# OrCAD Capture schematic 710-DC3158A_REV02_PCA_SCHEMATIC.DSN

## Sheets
1 PAGE1
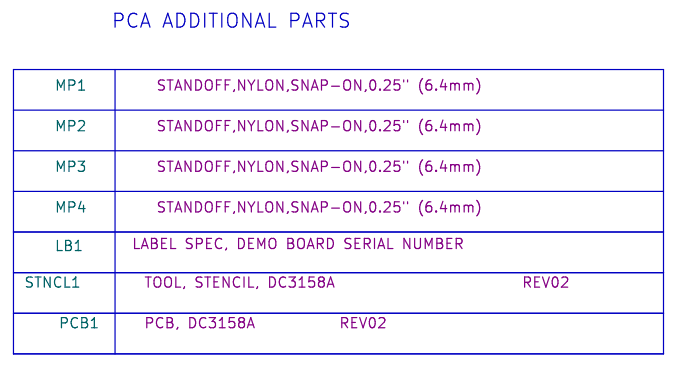
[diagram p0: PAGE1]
2 LT3041ADE: size B; title: LINEAR REGULATOR WITH VOIC CONTROL; note: 20V, 1A ULTRALOW NOISE, ULTRAHIGH PSRR
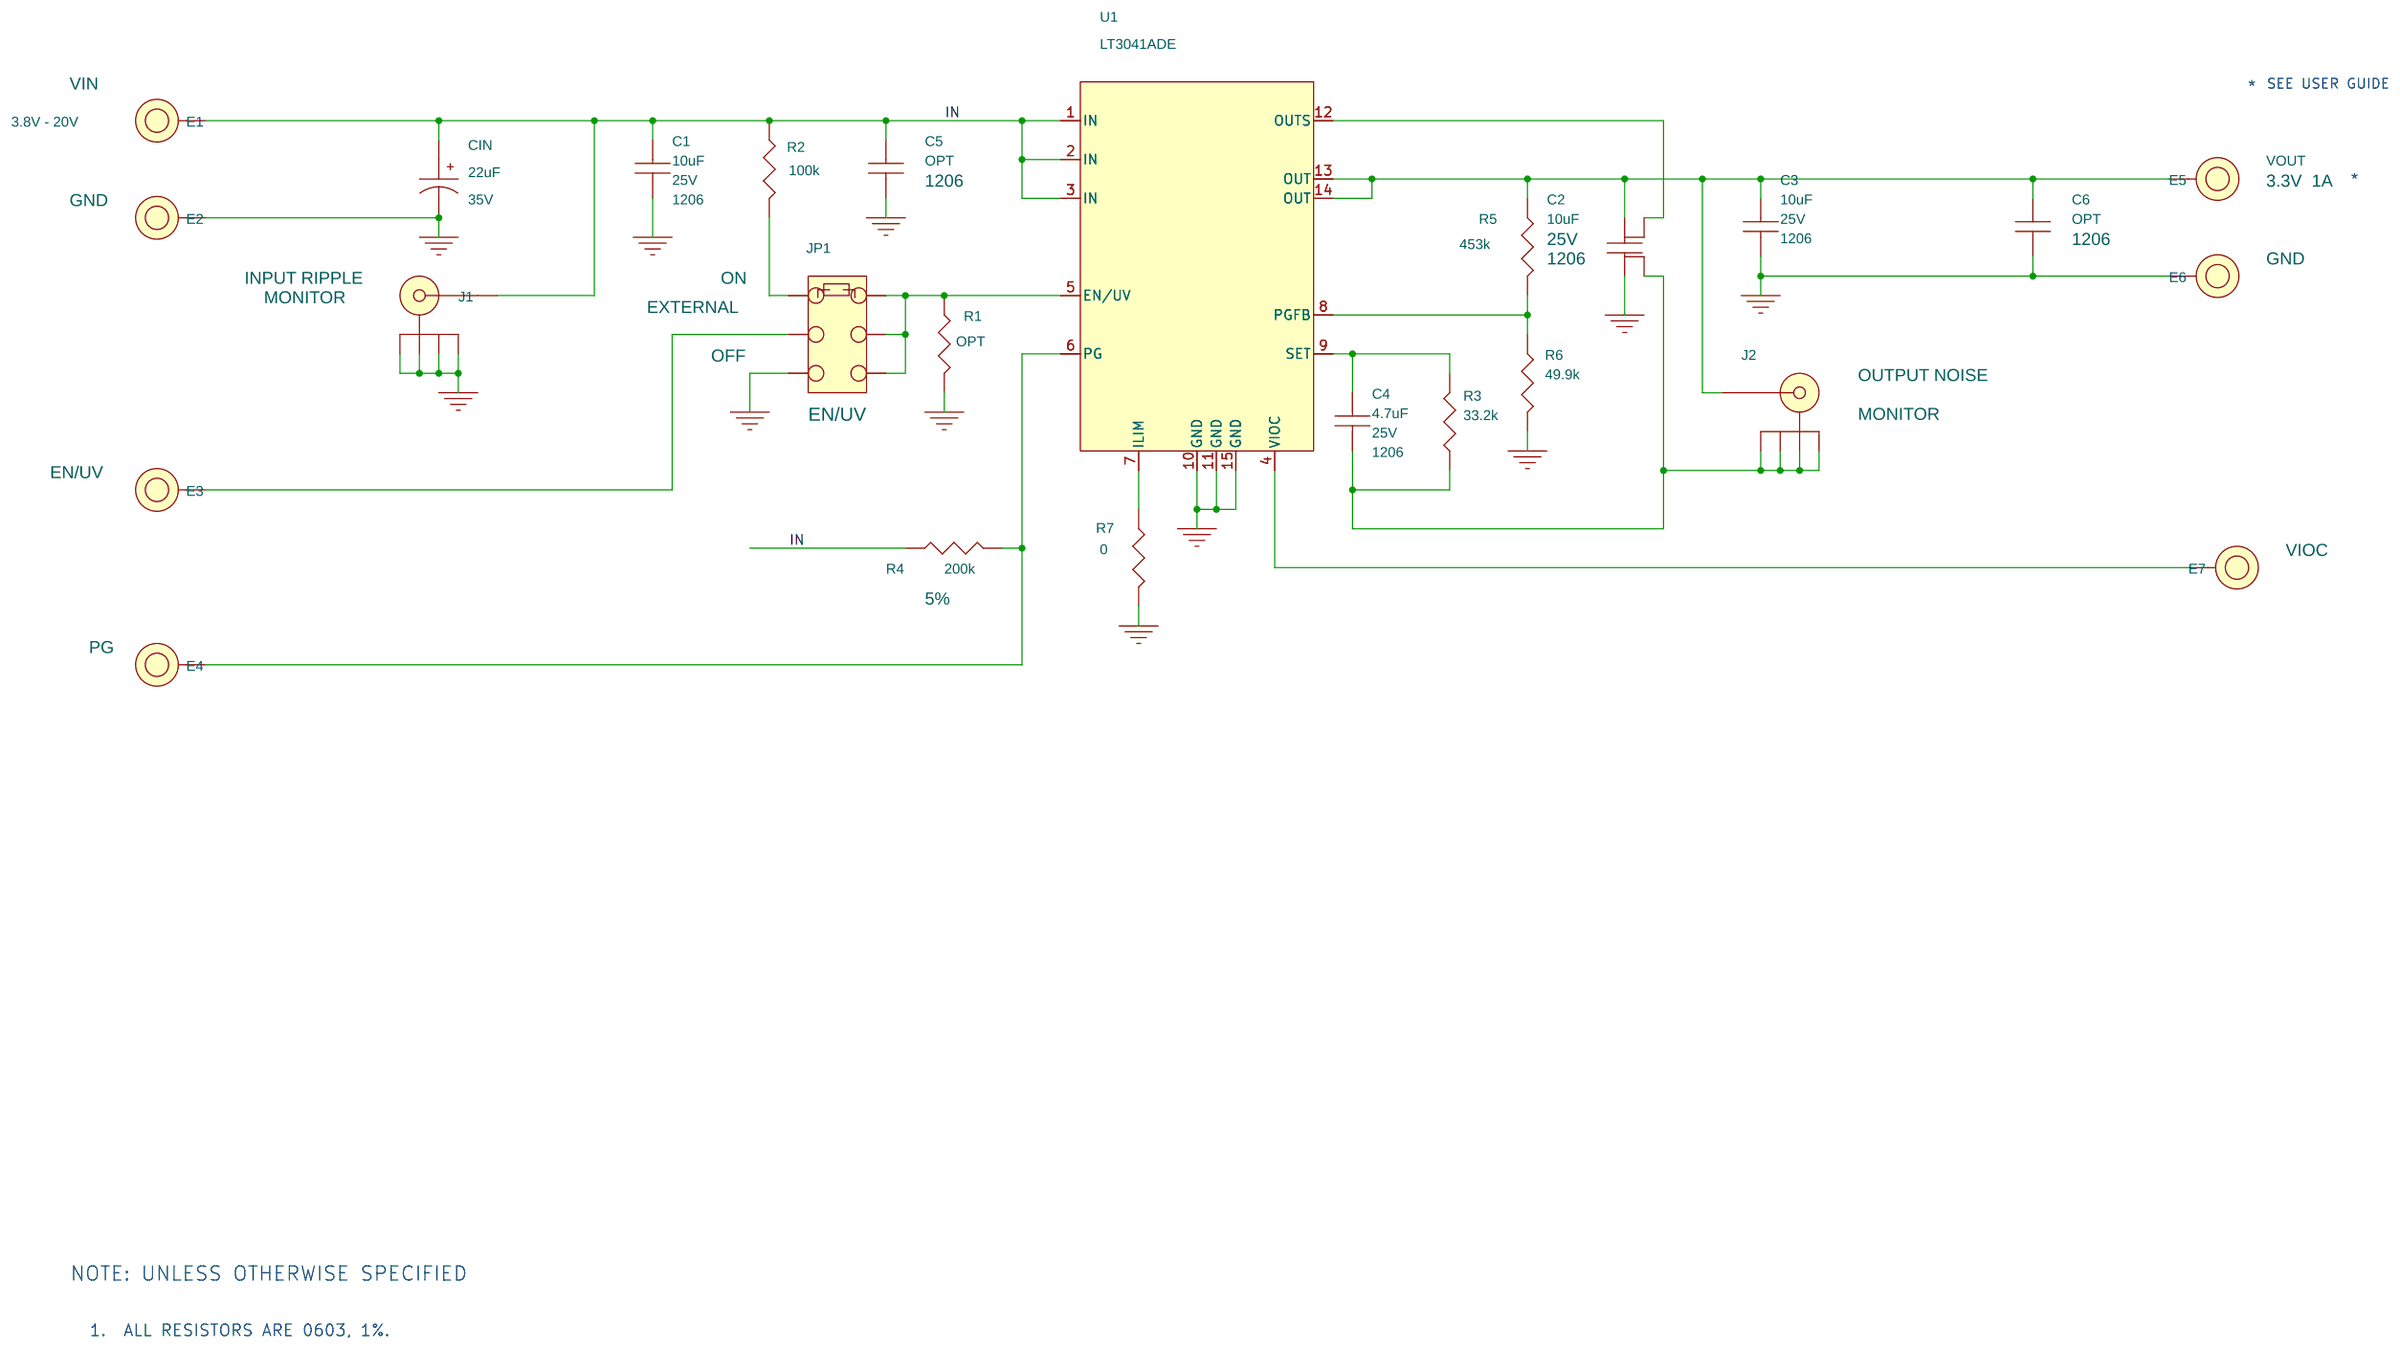
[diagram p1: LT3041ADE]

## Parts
sheet LT3041ADE
C1  10uF  [CC1206N]
C2  10uF  [1206-SP]
C3  10uF  [CC1206N]
C4  4.7uF  [CC1206N]
C5  OPT  [CC1206N]
C6  OPT  [CC1206N]
CIN  22uF  [SUNCON_CE-BSS_5X5.4]
E1  TEST POINT  [MILLMAX2501]
E2  TEST POINT  [MILLMAX2501]
E3  TEST POINT  [MILLMAX2501]
E4  TEST POINT  [MILLMAX2501]
E5  TEST POINT  [MILLMAX2501]
E6  TEST POINT  [MILLMAX2501]
E7  TEST POINT  [MILLMAX2501]
J1  RF,BNC  [CONNEX-112404]
J2  RF,BNC  [CONNEX-112404]
JP1  HDR  [HD2X3-079]
R1  OPT  [CR0603N]
R2  100k  [CR0603N]
R3  33.2k  [CR0603N]
R4  200k  [CR0603N]
R5  453k  [CR0603N]
R6  49.9k  [CR0603N]
R7  0  [CR0603N]
U1  LT3041ADE  [LTC-DFN-14-1708]
XJP1  SHUNT
sheet PAGE1
LB1  LABEL  [895-0154_REV01]
MP1  STANDOFF  [KEYSTONE_8829-8834]
MP2  STANDOFF  [KEYSTONE_8829-8834]
MP3  STANDOFF  [KEYSTONE_8829-8834]
MP4  STANDOFF  [KEYSTONE_8829-8834]
PCB1  PCB, DC3158A
STNCL1  TOOL, STENCIL, DC3158A

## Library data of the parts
C1 = CAP: CAP.,10uF,X7R,25V,10%,1206,AEC-Q200; 1ST PART FIELD: 25V; CLASS: DISCRETE; Dielectric Type: X7R; FPLIST: CC1206N,CC1206L,CC1206M; Inventory Qty: 13672; Manufacturer: TAIYO YUDEN; Manufacturer PN: TMK316AB7106KLHT; PART_NUMBER: 150-2466; Package Size: 1206; Package Type: SMD; Rated Voltage: 25V; Tolerance: 10%
C2 = CAP_3: CAP.,10uF,X7S,25V,10%,1206,AEC-Q200,NO SUBS ALLOWED; CLASS: DISCRETE; Dielectric Type: X7S; Inventory Qty: 7705; Manufacturer: MURATA; Manufacturer PN: GCM31CC71E106KA03L; PART_NUMBER: 150-1892; Package Size: 1206; Rated Voltage: 25V; Tolerance: 10%
C3 = CAP: CAP.,10uF,X7S,25V,10%,1206,AEC-Q200,NO SUBS ALLOWED; CLASS: DISCRETE; Dielectric Type: X7S; FPLIST: CC1206N,CC1206L,CC1206M; Inventory Qty: 0; Manufacturer: MURATA; Manufacturer PN: GCM31CC71E106KA03L; PART_NUMBER: 150-1892; Package Size: 1206; Rated Voltage: 25V; Tolerance: 10%
C4 = CAP: CAP.,4.7uF,X7R,25V,10%,1206,SOFT TERM,NO SUBS ALLOWED; 1ST PART FIELD: 25V; CLASS: DISCRETE; Dielectric Type: X7R; FPLIST: CC1206N,CC1206L,CC1206M; Inventory Qty: 0; Manufacturer: MURATA; Manufacturer PN: GCJ31CR71E475KA12L; PART_NUMBER: 150-1894; Package Size: 1206; Rated Voltage: 25V; Tolerance: 10%
C5 C6 = CAP: CAP., OPTION, 1206; 1ST PART FIELD: 50V; 2nd Part Field: 10uF; CLASS: DISCRETE; FPLIST: CC1206N,CC1206L,CC1206M; PART_NUMBER: 150-3160; Package Size: 1206; Package Type: SMD
CIN = CAP_P_ALT: CAP.,22uF,35V,20%,5X5.4mm; 1st Part Field: 35V; 5TH PART FIELD: 35CE22BSS; CLASS: DISCRETE; Dielectric Type: ALUM; FPLIST: SUNCON_CE-BSS_5X5.4,SUNCON_CE-BSS_5X5-4; Inventory Qty: 8056; Manufacturer: SUN ELECTRONIC INDUSTRIES CORP; Manufacturer PN: 35CE22BSS; PART_NUMBER: 150-0491; Package Size: 5X5.4mm; Rated Voltage: 35V; Tolerance: 20%
E1 = TESTPOINT_.219_MILL-MAX_2501_A: TEST POINT,TURRET,0.094" MTG. HOLE,PCB 0.062" THK; 1ST PART FIELD: *; 2nd Part Field: VIN; CLASS: IO; FPLIST: MILLMAX2501,MILLMAX2501-2; Inventory Qty: 823526; Manufacturer: MILL-MAX; Manufacturer PN: 2501-2-00-80-00-00-07-0; PART_NUMBER: 260-0003; Value1: 3.8V - 20V
E2 E6 = TESTPOINT_.219_MILL-MAX_2501_A: TEST POINT,TURRET,0.094" MTG. HOLE,PCB 0.062" THK; 1ST PART FIELD: GND; CLASS: IO; FPLIST: MILLMAX2501,MILLMAX2501-2; Inventory Qty: 823526; Manufacturer: MILL-MAX; Manufacturer PN: 2501-2-00-80-00-00-07-0; PART_NUMBER: 260-0003
E3 = TESTPOINT_.219_MILL-MAX_2501_A: TEST POINT,TURRET,0.094" MTG. HOLE,PCB 0.062" THK; 1ST PART FIELD: EN/UV; CLASS: IO; FPLIST: MILLMAX2501,MILLMAX2501-2; Inventory Qty: 823526; Manufacturer: MILL-MAX; Manufacturer PN: 2501-2-00-80-00-00-07-0; PART_NUMBER: 260-0003
E4 = TESTPOINT_.219_MILL-MAX_2501_A: TEST POINT,TURRET,0.094" MTG. HOLE,PCB 0.062" THK; 1ST PART FIELD: PG; CLASS: IO; FPLIST: MILLMAX2501,MILLMAX2501-2; Inventory Qty: 823526; Manufacturer: MILL-MAX; Manufacturer PN: 2501-2-00-80-00-00-07-0; PART_NUMBER: 260-0003
E5 = TESTPOINT_.219_MILL-MAX_2501_A: TEST POINT,TURRET,0.094" MTG. HOLE,PCB 0.062" THK; 1ST PART FIELD: 3.3V  1A; CLASS: IO; FPLIST: MILLMAX2501,MILLMAX2501-2; Inventory Qty: 823526; Manufacturer: MILL-MAX; Manufacturer PN: 2501-2-00-80-00-00-07-0; PART_NUMBER: 260-0003; VALUE1: VOUT
E7 = TESTPOINT_.219_MILL-MAX_2501_A: TEST POINT,TURRET,0.094" MTG. HOLE,PCB 0.062" THK; 1ST PART FIELD: VIOC; CLASS: IO; FPLIST: MILLMAX2501,MILLMAX2501-2; Inventory Qty: 823526; Manufacturer: MILL-MAX; Manufacturer PN: 2501-2-00-80-00-00-07-0; PART_NUMBER: 260-0003
J1 = BNC_50_OHM_112404_C: CONN.,RF,BNC,RCPT,JACK,5-PIN,ST,THT,50 OHMS; 1ST PART FIELD: INPUT RIPPLE; 2nd Part Field: MONITOR; CLASS: IO; Inventory Qty: 80023; Manufacturer: AMPHENOL RF; Manufacturer PN: 112404; PART_NUMBER: 250-0427
J2 = BNC_50_OHM_112404_C: CONN.,RF,BNC,RCPT,JACK,5-PIN,ST,THT,50 OHMS; 1ST PART FIELD: OUTPUT NOISE; 2nd Part Field: MONITOR; CLASS: IO; Inventory Qty: 80023; Manufacturer: AMPHENOL RF; Manufacturer PN: 112404; PART_NUMBER: 250-0427
JP1 = HEADER_2X3_.079: CONN.,HDR,MALE,2x3,2mm,VERT,ST,THT; 1st Part Field: ON; 2nd Part Field: EXTERNAL; 3rd Part Field: OFF; 9th Part Field: EN/UV; CLASS: IO; Inventory Qty: 17651; Manufacturer: WURTH ELEKTRONIK; Manufacturer PN: 62000621121; PART_NUMBER: 250-0483
R1 = RES: RES., OPTION, 0603; CLASS: DISCRETE; FPLIST: CR0603N,CR0603L,CR0603M; PART_NUMBER: 100-2374; Package Size: 0603; V: 1%
R2 = RES: RES.,100k OHMS,1%,1/10W,0603,AEC-Q200; CLASS: DISCRETE; FPLIST: CR0603N,CR0603L,CR0603M; Inventory Qty: 40430; Manufacturer: PANASONIC; Manufacturer PN: ERJ3EKF1003V; PART_NUMBER: 100-0981; Package Size: 0603; Rated Power: 1/10W; Temperature Coefficient: 100ppm; Tolerance: 1%; V: 1%
R3 = RES: RES.,33.2k OHMS,1%,1/10W,0603; CLASS: DISCRETE; FPLIST: CR0603N,CR0603L,CR0603M; Inventory Qty: 55894; Manufacturer: PANASONIC; Manufacturer PN: ERJ3EKF3322V; PART_NUMBER: 100-2634; Package Size: 0603; Rated Power: 1/10W; Temperature Coefficient: 100ppm; Tolerance: 1%; V: 1%
R4 = RES: RES.,200k OHMS,5%,1/10W,0603,AEC-Q200; CLASS: DISCRETE; FPLIST: CR0603N,CR0603L,CR0603M; Inventory Qty: 3771; Manufacturer: NIC; Manufacturer PN: NRC06J204TRF; PART_NUMBER: 100-2589; Package Size: 0603; Rated Power: 1/10W; Temperature Coefficient: 200ppm/C; Tolerance: 5%
R5 = RES: RES.,453k OHMS,1%,1/10W,0603,AEC-Q200; CLASS: DISCRETE; FPLIST: CR0603N,CR0603L,CR0603M; Inventory Qty: 14516; Manufacturer: VISHAY; Manufacturer PN: CRCW0603453KFKEA; PART_NUMBER: 100-2877; Package Size: 0603; Rated Power: 1/10W; Temperature Coefficient: 100PPM; Tolerance: 1%; V: 1%
R6 = RES: RES.,49.9k OHMS,1%,1/10W,0603; CLASS: DISCRETE; FPLIST: CR0603N,CR0603L,CR0603M; Inventory Qty: 100527; Manufacturer: NIC; Manufacturer PN: NRC06F4992TRF; PART_NUMBER: 100-0303; Package Size: 0603; Rated Power: 1/10W; Temperature Coefficient: 100ppm/C; Tolerance: 1%; V: 1%
R7 = RES: RES.,0 OHM,1/10W,0603,AEC-Q200; CLASS: DISCRETE; FPLIST: CR0603N,CR0603L,CR0603M; Inventory Qty: 676258; Manufacturer: VISHAY; Manufacturer PN: CRCW06030000Z0EA; PART_NUMBER: 100-0009; Package Size: 0603; Rated Power: 1/10W; V: 1%
U1 = LT3041-DD: IC,20V,1A ULTRALOW NOISE,ULTRAHIGH PSRR LINEAR REG.,DFN14DE-4X3; CLASS: IC; Inventory Qty: 0; Manufacturer: ANALOG DEVICES; Manufacturer PN: LT3041ADE#PBF; PART_NUMBER: LT3041ADE#PBF; Package Type: DFN14DE-4X3
XJP1 = SHUNT_2MM_C: CONN.,SHUNT,FEMALE,2-POS,2mm; CLASS: IO; Inventory Qty: 64675; Manufacturer: Wurth Elektronik; Manufacturer PN: 60800213421; PART_NUMBER: 250-0485
LB1 = BLANK_LABEL: LABEL SPEC, DEMO BOARD SERIAL NUMBER; Inventory Qty: 0; Manufacturer: BRADY; Manufacturer PN: THT-96-717-10; PART_NUMBER: 895-0154
MP1-MP4 = BLANK_MECHANICAL_PART: STANDOFF,NYLON,SNAP-ON,0.25" (6.4mm); CLASS: DISCRETE; FPLIST: KEYSTONE_8829-8834,KEYSTONE_8831,MTG-8831; Inventory Qty: 227624; Manufacturer: KEYSTONE; Manufacturer PN: 8831; PART_NUMBER: 763-0006
PCB1 = BLANK_PCB_PART: BOM Notes: REV02; CLASS: DISCRETE; Inventory Qty: 0; Manufacturer: ADI APPROVED SUPPLIER; Manufacturer PN: 600-DC3158A; PART_NUMBER: 600-DC3158A
STNCL1 = BLANK_STENCIL_PART: BOM Notes: REV02; CLASS: DISCRETE; Inventory Qty: 0; Manufacturer: ADI APPROVED SUPPLIER; Manufacturer PN: 830-DC3158A; PART_NUMBER: 830-DC3158A

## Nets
GND: C1.2 C2.1 C3.2 C5.2 C6.2 CIN.2 E2.1 E6.1 J1.2 J1.3 J1.4 J1.5 JP1.5 R1.2 R6.2 R7.2 U1.10(GND) U1.11(GND) U1.15(GND)
IN: C1.1 C5.1 CIN.1 E1.1 J1.1 R2.1 R4.2 U1.1(IN) U1.2(IN) U1.3(IN)
N16788606: E4.1 R4.1 U1.6(PG)
N16788632: C4.1 R3.2 U1.9(SET)
N16788734: C2.3 C4.2 J2.2 J2.3 J2.4 J2.5 R3.1
N16788758: R5.2 R6.1 U1.8(PGFB)
N16788760: C2.4 C3.1 C6.1 E5.1 J2.1 R5.1 U1.13(OUT) U1.14(OUT)
N16831703: E3.1 JP1.3
N16883314: C2.2 U1.12(OUTS)
N16887322: E7.1 U1.4(VIOC)
N16887886: R7.1 U1.7(ILIM)
N16893765: JP1.1 R2.2
N16907985: JP1.2 JP1.4 JP1.6 R1.1 U1.5(EN/UV)

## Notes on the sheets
sheet 1
- PCA ADDITIONAL PARTS
sheet 2
- *
- SEE USER GUIDE
- *
- NOTE: UNLESS OTHERWISE SPECIFIED
- 1.  ALL RESISTORS ARE 0603, 1%.
